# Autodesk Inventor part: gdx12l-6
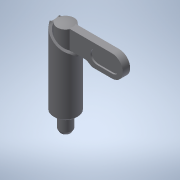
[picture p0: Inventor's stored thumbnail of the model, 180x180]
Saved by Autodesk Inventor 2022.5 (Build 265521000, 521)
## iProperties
Created: 2016-12
Part Number: gdx12l-6
Material: 一般
Document SubType Name: Modeling
Designer: imaocorp
Density: 1 g/cm^3
Appearance: 既定
Author: imaocorp
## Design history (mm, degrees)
node "gdx12l-6.x_t1"
node "gdx12l-6"
node "Base1"
